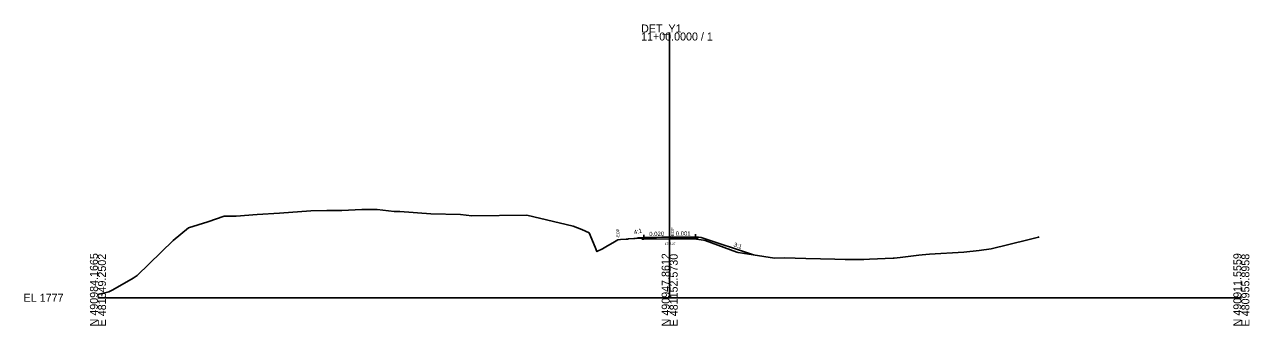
# Model space of a CAD drawing. Extents: x -26 to 403, y -10 to 3149.
# Drawn here: x -25.7 to 402.8, y 990.3 to 1095.6 of the extents above; entities that cross this region are included whole.
import ezdxf

# ---------------------------------------------------------------- set-up
doc = ezdxf.new("R2010")
doc.units = 0
for name, color, linetype in [('Exist Cross Section Cell', 7, 'Continuous'), ('Exist XS Center Line Elevation Label', 7, 'Continuous'), ('Exist XS Ground Line', 7, 'Continuous'), ('Prop XS Ditch Slope Text', 7, 'Continuous'), ('Prop XS Dump Level', 7, 'Continuous'), ('Prop XS EOT Tick Mark', 7, 'Continuous'), ('Prop XS Finish Grade', 7, 'Continuous'), ('Prop XS Finish Grade Earthwork', 7, 'Continuous'), ('Prop XS Finish Grade Pavement', 7, 'Continuous'), ('Prop XS Pvmt Edge Slope', 7, 'Continuous'), ('Prop XS SE Text', 7, 'Continuous'), ('Prop XS Side Slope Text', 7, 'Continuous'), ('Prop XS Subgrade Earthwork', 7, 'Continuous'), ('Scratch_Level_3', 7, 'Continuous'), ('Scratch_Level_4', 7, 'Continuous')]:
    doc.layers.add(name, color=color, linetype=linetype)

msp = doc.modelspace()

# ---------------------------------------------------------------- linework, layer by layer
at = {"layer": 'Exist Cross Section Cell'}
for p, q in [((200, 1000), (200, 1092.82)), ((0, 1000), (200, 1000)), ((200, 1000), (400, 1000))]:
    msp.add_line(p, q, dxfattribs=at)
at = {"layer": 'Exist XS Ground Line'}
msp.add_lwpolyline([(0, 1001.11), (3.78, 1002.03), (5.18, 1002.8), (12.37, 1006.92), (13.7, 1007.82), (26.36, 1020.01), (31.72, 1024.48), (38.42, 1026.63), (44.21, 1028.59), (48.32, 1028.57), (55.73, 1029.13), (63.51, 1029.61), (74.46, 1030.42), (80.03, 1030.55), (85.36, 1030.6), (92.31, 1030.94), (97.68, 1030.9), (103.67, 1030.19), (105.65, 1030.19), (116.45, 1029.43), (126.78, 1029.14), (130.78, 1028.66), (149.98, 1028.86), (166.24, 1025.05), (169.32, 1023.88), (171.83, 1022.76), (173.89, 1017.69), (174.56, 1016.19), (176.5, 1017.17), (177.66, 1017.82), (180.73, 1019.6), (181.89, 1020.28), (182.85, 1020.38), (184.83, 1020.54), (185.25, 1020.57), (185.59, 1020.6), (187.41, 1020.7), (187.88, 1020.72), (190.49, 1020.85), (191.44, 1020.91), (191.94, 1020.94), (192.85, 1020.99), (194.1, 1021.05), (195.39, 1021.12), (197.24, 1021.19), (197.93, 1021.22), (200.34, 1021.28), (200.99, 1021.27), (202.58, 1021.17), (206.2, 1020.97), (211.8, 1020.15), (212.4, 1020.07), (223.48, 1016.02), (223.92, 1015.83), (225.43, 1015.65), (236.72, 1013.89), (240.15, 1013.98), (247.63, 1013.73), (252.78, 1013.66), (257.8, 1013.57), (261.36, 1013.42), (267.97, 1013.43), (269.95, 1013.52), (278.14, 1013.82), (278.54, 1013.85), (280.67, 1014.12), (287.12, 1014.91), (288.31, 1015.06), (290.95, 1015.31), (302.94, 1016.01), (308.28, 1016.59), (312.51, 1017.14), (325.26, 1020.31), (329, 1021.26), (329.31, 1021.29)], dxfattribs=at)
at = {"layer": 'Prop XS Dump Level'}
for p, q in [((191, 1021.04), (200, 1021.22)), ((200, 1021.22), (209, 1021.22))]:
    msp.add_line(p, q, dxfattribs=at)
at = {"layer": 'Prop XS EOT Tick Mark'}
for p, q in [((191, 1021.04), (191, 1022.04)), ((209, 1021.22), (209, 1022.22))]:
    msp.add_line(p, q, dxfattribs=at)
at = {"layer": 'Prop XS Finish Grade'}
for p, q in [((191, 1021.04), (189.91, 1020.99)), ((209, 1021.22), (210.09, 1021.18))]:
    msp.add_line(p, q, dxfattribs=at)
at = {"layer": 'Prop XS Finish Grade Earthwork'}
for p, q in [((189, 1020.96), (188.11, 1020.73)), ((189, 1020.96), (189.91, 1020.99)), ((210.09, 1021.18), (211, 1021.14)), ((211, 1021.14), (229.28, 1015.05))]:
    msp.add_line(p, q, dxfattribs=at)
at = {"layer": 'Prop XS Finish Grade Pavement'}
for p, q in [((191, 1021.04), (200, 1021.22)), ((200, 1021.22), (209, 1021.22))]:
    msp.add_line(p, q, dxfattribs=at)
at = {"layer": 'Prop XS Pvmt Edge Slope'}
for p, q in [((191, 1021.04), (190.44, 1020.47)), ((209, 1021.22), (209.56, 1020.66))]:
    msp.add_line(p, q, dxfattribs=at)
at = {"layer": 'Prop XS Subgrade Earthwork'}
for p, q in [((190.44, 1020.47), (189.91, 1020.99)), ((191, 1020.5), (190.44, 1020.47)), ((200, 1020.68), (191, 1020.5)), ((209, 1020.68), (200, 1020.68)), ((209, 1020.68), (209.56, 1020.66)), ((209.56, 1020.66), (210.09, 1021.18))]:
    msp.add_line(p, q, dxfattribs=at)
at = {"layer": 'Scratch_Level_4'}
for p, q in [((189, 1020.96), (188.11, 1020.73)), ((189, 1020.96), (189.91, 1020.99)), ((191, 1021.04), (189.91, 1020.99)), ((191, 1021.04), (200, 1021.22)), ((200, 1021.22), (209, 1021.22)), ((209, 1021.22), (210.09, 1021.18)), ((210.09, 1021.18), (211, 1021.14)), ((211, 1021.14), (229.28, 1015.05))]:
    msp.add_line(p, q, dxfattribs=at)

# ---------------------------------------------------------------- texts
at = {"layer": 'Exist Cross Section Cell'}
for s, p in [('11+00.0000 / 1', (190, 1090.02)), ('DET_Y1', (190, 1092.82)), ('EL 1777', (-26, 998.6))]:
    msp.add_text(s, height=2.8, dxfattribs=at).set_placement(p)
for s, p in [('N 490984.1665', (0, 990)), ('E 481349.2502', (2.8, 990)), ('N 490947.8612', (200, 990)), ('E 481152.5730', (202.8, 990)), ('N 490911.5559', (400, 990)), ('E 480955.8958', (402.8, 990))]:
    msp.add_text(s, height=2.8, rotation=90, dxfattribs=at).set_placement(p)
at = {"layer": 'Exist XS Center Line Elevation Label'}
msp.add_text('1798.27', height=0.75, dxfattribs=at).set_placement((198.28, 1018.52))
at = {"layer": 'Prop XS Ditch Slope Text'}
msp.add_text('4:1', height=1.5, rotation=14.0362, dxfattribs=at).set_placement((187.64, 1022.16))
at = {"layer": 'Prop XS SE Text'}
for s, rotation, p in [('0.020', 1.1458, (192.88, 1021.57)), ('0.001', 0.0425, (202.15, 1021.72))]:
    msp.add_text(s, height=1.5, rotation=rotation, dxfattribs=at).set_placement(p)
at = {"layer": 'Prop XS Side Slope Text'}
msp.add_text('3:1', height=1.5, rotation=341.5651, dxfattribs=at).set_placement((222.25, 1018))
at = {"layer": 'Scratch_Level_3'}
for p in [(201.49, 1021.22), (182.39, 1020.83)]:
    msp.add_text('-EOP', height=1, rotation=90, dxfattribs=at).set_placement(p)

doc.saveas('drawing.dxf')
